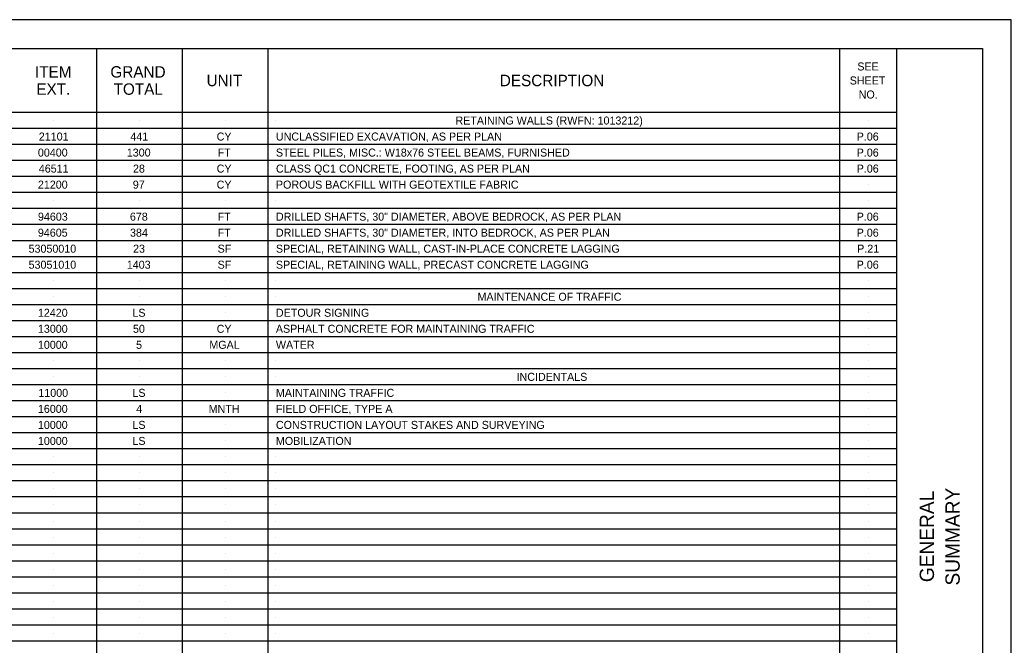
# Model space of a CAD drawing. Extents: x 0 to 34, y 0 to 22.
# Drawn here: x 16.66 to 34, y 11.07 to 22 of the extents above; entities that cross this region are included whole.
import ezdxf

# ---------------------------------------------------------------- set-up
doc = ezdxf.new("R2010")
doc.units = 0
for name, color, linetype in [('RD_P_Text', 7, 'Continuous'), ('SC_Scratch1', 7, 'Continuous'), ('SH_Border', 7, 'Continuous'), ('SH_Cut_Line', 7, 'Continuous'), ('SH_Data', 7, 'Continuous')]:
    doc.layers.add(name, color=color, linetype=linetype)

msp = doc.modelspace()

# ---------------------------------------------------------------- linework, layer by layer
at = {"layer": 'SC_Scratch1'}
for p, q in [((17.25, 20.24), (17.25, 20.24)), ((18.75, 20.24), (18.75, 20.24)), ((20.25, 20.24), (20.25, 20.24)), ((21.14, 20.24), (21.14, 20.24)), ((31.5, 20.24), (31.5, 20.24)), ((17.25, 19.96), (17.25, 19.96)), ((18.75, 19.96), (18.75, 19.96)), ((20.25, 19.96), (20.25, 19.96)), ((21.14, 19.96), (21.14, 19.96)), ((31.5, 19.96), (31.5, 19.96)), ((17.25, 19.68), (17.25, 19.68)), ((18.75, 19.68), (18.75, 19.68)), ((20.25, 19.68), (20.25, 19.68)), ((21.14, 19.68), (21.14, 19.68)), ((31.5, 19.68), (31.5, 19.68)), ((17.25, 19.4), (17.25, 19.4)), ((18.75, 19.4), (18.75, 19.4)), ((20.25, 19.4), (20.25, 19.4)), ((21.14, 19.4), (21.14, 19.4)), ((31.5, 19.4), (31.5, 19.4)), ((17.25, 19.12), (17.25, 19.12)), ((18.75, 19.12), (18.75, 19.12)), ((20.25, 19.12), (20.25, 19.12)), ((21.14, 19.12), (21.14, 19.12)), ((31.5, 19.12), (31.5, 19.12)), ((17.25, 18.84), (17.25, 18.84)), ((18.75, 18.84), (18.75, 18.84)), ((20.25, 18.84), (20.25, 18.84)), ((21.14, 18.84), (21.14, 18.84)), ((31.5, 18.84), (31.5, 18.84)), ((17.25, 18.56), (17.25, 18.56)), ((18.75, 18.56), (18.75, 18.56)), ((20.25, 18.56), (20.25, 18.56)), ((21.14, 18.56), (21.14, 18.56)), ((31.5, 18.56), (31.5, 18.56)), ((17.25, 18.28), (17.25, 18.28)), ((18.75, 18.28), (18.75, 18.28)), ((20.25, 18.28), (20.25, 18.28)), ((21.14, 18.28), (21.14, 18.28)), ((31.5, 18.28), (31.5, 18.28)), ((17.25, 18), (17.25, 18)), ((18.75, 18), (18.75, 18)), ((20.25, 18), (20.25, 18)), ((21.14, 18), (21.14, 18)), ((31.5, 18), (31.5, 18)), ((17.25, 17.72), (17.25, 17.72)), ((18.75, 17.72), (18.75, 17.72)), ((20.25, 17.72), (20.25, 17.72)), ((21.14, 17.72), (21.14, 17.72)), ((31.5, 17.72), (31.5, 17.72)), ((17.25, 17.44), (17.25, 17.44)), ((18.75, 17.44), (18.75, 17.44)), ((20.25, 17.44), (20.25, 17.44)), ((21.14, 17.44), (21.14, 17.44)), ((31.5, 17.44), (31.5, 17.44)), ((17.25, 17.16), (17.25, 17.16)), ((18.75, 17.16), (18.75, 17.16)), ((20.25, 17.16), (20.25, 17.16)), ((21.14, 17.16), (21.14, 17.16)), ((31.5, 17.16), (31.5, 17.16)), ((17.25, 16.88), (17.25, 16.88)), ((18.75, 16.88), (18.75, 16.88)), ((20.25, 16.88), (20.25, 16.88)), ((21.14, 16.88), (21.14, 16.88)), ((31.5, 16.88), (31.5, 16.88)), ((17.25, 16.6), (17.25, 16.6)), ((18.75, 16.6), (18.75, 16.6)), ((20.25, 16.6), (20.25, 16.6)), ((21.14, 16.6), (21.14, 16.6)), ((31.5, 16.6), (31.5, 16.6)), ((17.25, 16.32), (17.25, 16.32)), ((18.75, 16.32), (18.75, 16.32)), ((20.25, 16.32), (20.25, 16.32)), ((21.14, 16.32), (21.14, 16.32)), ((31.5, 16.32), (31.5, 16.32)), ((17.25, 16.04), (17.25, 16.04)), ((18.75, 16.04), (18.75, 16.04)), ((20.25, 16.04), (20.25, 16.04)), ((21.14, 16.04), (21.14, 16.04)), ((31.5, 16.04), (31.5, 16.04)), ((17.25, 15.76), (17.25, 15.76)), ((18.75, 15.76), (18.75, 15.76)), ((20.25, 15.76), (20.25, 15.76)), ((21.14, 15.76), (21.14, 15.76)), ((31.5, 15.76), (31.5, 15.76)), ((17.25, 15.48), (17.25, 15.48)), ((18.75, 15.48), (18.75, 15.48)), ((20.25, 15.48), (20.25, 15.48)), ((21.14, 15.48), (21.14, 15.48)), ((31.5, 15.48), (31.5, 15.48)), ((17.25, 15.2), (17.25, 15.2)), ((18.75, 15.2), (18.75, 15.2)), ((20.25, 15.2), (20.25, 15.2)), ((21.14, 15.2), (21.14, 15.2)), ((31.5, 15.2), (31.5, 15.2)), ((17.25, 14.92), (17.25, 14.92)), ((18.75, 14.92), (18.75, 14.92)), ((20.25, 14.92), (20.25, 14.92)), ((21.14, 14.92), (21.14, 14.92)), ((31.5, 14.92), (31.5, 14.92)), ((17.25, 14.64), (17.25, 14.64)), ((18.75, 14.64), (18.75, 14.64)), ((20.25, 14.64), (20.25, 14.64)), ((21.14, 14.64), (21.14, 14.64)), ((31.5, 14.64), (31.5, 14.64)), ((17.25, 14.36), (17.25, 14.36)), ((18.75, 14.36), (18.75, 14.36)), ((20.25, 14.36), (20.25, 14.36)), ((21.14, 14.36), (21.14, 14.36)), ((31.5, 14.36), (31.5, 14.36)), ((17.25, 14.08), (17.25, 14.08)), ((18.75, 14.08), (18.75, 14.08)), ((20.25, 14.08), (20.25, 14.08)), ((21.14, 14.08), (21.14, 14.08)), ((31.5, 14.08), (31.5, 14.08)), ((17.25, 13.8), (17.25, 13.8)), ((18.75, 13.8), (18.75, 13.8)), ((20.25, 13.8), (20.25, 13.8)), ((21.14, 13.8), (21.14, 13.8)), ((31.5, 13.8), (31.5, 13.8)), ((17.25, 13.52), (17.25, 13.52)), ((18.75, 13.52), (18.75, 13.52)), ((20.25, 13.52), (20.25, 13.52)), ((21.14, 13.52), (21.14, 13.52)), ((31.5, 13.52), (31.5, 13.52)), ((17.25, 13.24), (17.25, 13.24)), ((18.75, 13.24), (18.75, 13.24)), ((20.25, 13.24), (20.25, 13.24)), ((21.14, 13.24), (21.14, 13.24)), ((31.5, 13.24), (31.5, 13.24)), ((17.25, 12.96), (17.25, 12.96)), ((18.75, 12.96), (18.75, 12.96)), ((20.25, 12.96), (20.25, 12.96)), ((21.14, 12.96), (21.14, 12.96)), ((31.5, 12.96), (31.5, 12.96)), ((17.25, 12.68), (17.25, 12.68)), ((18.75, 12.68), (18.75, 12.68)), ((20.25, 12.68), (20.25, 12.68)), ((21.14, 12.68), (21.14, 12.68)), ((31.5, 12.68), (31.5, 12.68)), ((17.25, 12.4), (17.25, 12.4)), ((18.75, 12.4), (18.75, 12.4)), ((20.25, 12.4), (20.25, 12.4)), ((21.14, 12.4), (21.14, 12.4)), ((31.5, 12.4), (31.5, 12.4)), ((17.25, 12.12), (17.25, 12.12)), ((18.75, 12.12), (18.75, 12.12)), ((20.25, 12.12), (20.25, 12.12)), ((21.14, 12.12), (21.14, 12.12)), ((31.5, 12.12), (31.5, 12.12)), ((17.25, 11.84), (17.25, 11.84)), ((18.75, 11.84), (18.75, 11.84)), ((20.25, 11.84), (20.25, 11.84)), ((21.14, 11.84), (21.14, 11.84)), ((31.5, 11.84), (31.5, 11.84)), ((17.25, 11.56), (17.25, 11.56)), ((18.75, 11.56), (18.75, 11.56)), ((20.25, 11.56), (20.25, 11.56)), ((21.14, 11.56), (21.14, 11.56)), ((31.5, 11.56), (31.5, 11.56)), ((17.25, 11.28), (17.25, 11.28)), ((18.75, 11.28), (18.75, 11.28)), ((20.25, 11.28), (20.25, 11.28)), ((21.14, 11.28), (21.14, 11.28)), ((31.5, 11.28), (31.5, 11.28))]:
    msp.add_line(p, q, dxfattribs=at)
at = {"layer": 'SH_Border'}
msp.add_line((32, 0.5), (32, 21.5), dxfattribs=at)
msp.add_lwpolyline([(1.5, 21.5), (33.5, 21.5), (33.5, 0.5), (1.5, 0.5)], close=True, dxfattribs=at)
at = {"layer": 'SH_Cut_Line'}
msp.add_lwpolyline([(0, 0), (34, 0), (34, 22), (0, 22)], close=True, dxfattribs=at)
at = {"layer": 'SH_Data'}
for p, q in [((18, 21.5), (18, 0.5)), ((19.5, 21.5), (19.5, 0.5)), ((21, 21.5), (21, 0.5)), ((31, 21.5), (31, 0.5)), ((32, 20.38), (1.5, 20.38)), ((32, 20.1), (1.5, 20.1)), ((32, 19.82), (1.5, 19.82)), ((32, 19.54), (1.5, 19.54)), ((32, 19.26), (1.5, 19.26)), ((32, 18.98), (1.5, 18.98)), ((32, 18.7), (1.5, 18.7)), ((32, 18.42), (1.5, 18.42)), ((32, 18.14), (1.5, 18.14)), ((32, 17.86), (1.5, 17.86)), ((32, 17.58), (1.5, 17.58)), ((32, 17.3), (1.5, 17.3)), ((32, 17.02), (1.5, 17.02)), ((32, 16.74), (1.5, 16.74)), ((32, 16.46), (1.5, 16.46)), ((32, 16.18), (1.5, 16.18)), ((32, 15.9), (1.5, 15.9)), ((32, 15.62), (1.5, 15.62)), ((32, 15.34), (1.5, 15.34)), ((32, 15.06), (1.5, 15.06)), ((32, 14.78), (1.5, 14.78)), ((32, 14.5), (1.5, 14.5)), ((32, 14.22), (1.5, 14.22)), ((32, 13.94), (1.5, 13.94)), ((32, 13.66), (1.5, 13.66)), ((32, 13.38), (1.5, 13.38)), ((32, 13.1), (1.5, 13.1)), ((32, 12.82), (1.5, 12.82)), ((32, 12.54), (1.5, 12.54)), ((32, 12.26), (1.5, 12.26)), ((32, 11.98), (1.5, 11.98)), ((32, 11.7), (1.5, 11.7)), ((32, 11.42), (1.5, 11.42)), ((32, 11.14), (1.5, 11.14))]:
    msp.add_line(p, q, dxfattribs=at)

# ---------------------------------------------------------------- texts
at = {"layer": 'RD_P_Text'}
for s, p in [('RETAINING WALLS (RWFN: 1013212)', (24.28, 20.17)), ('21101', (16.993, 19.89)), ('441', (18.594, 19.89)), ('CY', (20.104, 19.89)), ('UNCLASSIFIED EXCAVATION, AS PER PLAN', (21.14, 19.89)), ('P.06', (31.298, 19.89)), ('00400', (16.977, 19.61)), ('1300', (18.532, 19.61)), ('FT', (20.121, 19.61)), ('STEEL PILES, MISC.: W18x76 STEEL BEAMS, FURNISHED', (21.14, 19.61)), ('P.06', (31.298, 19.61)), ('46511', (16.993, 19.33)), ('28', (18.64, 19.33)), ('CY', (20.104, 19.33)), ('CLASS QC1 CONCRETE, FOOTING, AS PER PLAN', (21.14, 19.33)), ('P.06', (31.298, 19.33)), ('21200', (16.977, 19.05)), ('97', (18.637, 19.05)), ('CY', (20.104, 19.05)), ('POROUS BACKFILL WITH GEOTEXTILE FABRIC', (21.14, 19.05)), ('94603', (16.978, 18.49)), ('678', (18.586, 18.49)), ('FT', (20.121, 18.49)), ('DRILLED SHAFTS, 30" DIAMETER, ABOVE BEDROCK, AS PER PLAN', (21.14, 18.49)), ('P.06', (31.298, 18.49)), ('94605', (16.977, 18.21)), ('384', (18.588, 18.21)), ('FT', (20.121, 18.21)), ('DRILLED SHAFTS, 30" DIAMETER, INTO BEDROCK, AS PER PLAN', (21.14, 18.21)), ('P.06', (31.298, 18.21)), ('53050010', (16.814, 17.93)), ('23', (18.641, 17.93)), ('SF', (20.12, 17.93)), ('SPECIAL, RETAINING WALL, CAST-IN-PLACE CONCRETE LAGGING', (21.14, 17.93)), ('P.21', (31.306, 17.93)), ('53051010', (16.814, 17.65)), ('1403', (18.532, 17.65)), ('SF', (20.12, 17.65)), ('SPECIAL, RETAINING WALL, PRECAST CONCRETE LAGGING', (21.14, 17.65)), ('P.06', (31.298, 17.65)), ('MAINTENANCE OF TRAFFIC', (24.666, 17.09)), ('12420', (16.977, 16.81)), ('LS', (18.63, 16.81)), ('DETOUR SIGNING', (21.14, 16.81)), ('13000', (16.977, 16.53)), ('50', (18.64, 16.53)), ('CY', (20.104, 16.53)), ('ASPHALT CONCRETE FOR MAINTAINING TRAFFIC', (21.139, 16.53)), ('10000', (16.977, 16.25)), ('5', (18.694, 16.25)), ('MGAL', (19.976, 16.25)), ('WATER', (21.14, 16.25)), ('INCIDENTALS', (25.349, 15.69)), ('11000', (16.985, 15.41)), ('LS', (18.63, 15.41)), ('MAINTAINING TRAFFIC', (21.14, 15.41)), ('16000', (16.977, 15.13)), ('4', (18.697, 15.13)), ('MNTH', (19.964, 15.13)), ('FIELD OFFICE, TYPE A', (21.14, 15.13)), ('10000', (16.977, 14.85)), ('LS', (18.63, 14.85)), ('CONSTRUCTION LAYOUT STAKES AND SURVEYING', (21.14, 14.85)), ('10000', (16.977, 14.57)), ('LS', (18.63, 14.57)), ('MOBILIZATION', (21.14, 14.57))]:
    msp.add_text(s, height=0.14, dxfattribs=at).set_placement(p)
at = {"layer": 'SH_Data'}
for s, height, p in [('ITEM', 0.2, (16.926, 20.99)), ('GRAND', 0.2, (18.245, 20.99)), ('SEE', 0.14, (31.309, 21.115)), ('UNIT', 0.2, (19.927, 20.84)), ('DESCRIPTION', 0.2, (25.056, 20.84)), ('SHEET', 0.14, (31.176, 20.87)), ('EXT.', 0.2, (16.949, 20.69)), ('TOTAL', 0.2, (18.301, 20.69)), ('NO.', 0.14, (31.333, 20.625))]:
    msp.add_text(s, height=height, dxfattribs=at).set_placement(p)
for s, p in [('GENERAL', (32.65, 12.171)), ('SUMMARY', (33.1, 12.112))]:
    msp.add_text(s, height=0.25, rotation=90, dxfattribs=at).set_placement(p)

doc.saveas('drawing.dxf')
